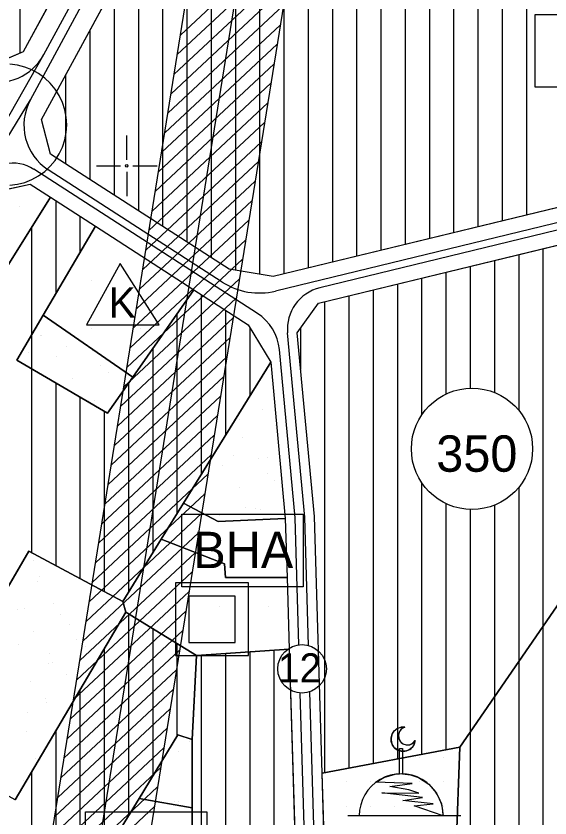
# Model space of a CAD drawing. Extents: x 419109 to 421295, y 4452223 to 4457798.
# Drawn here: x 419454.4 to 419674.5, y 4452731.2 to 4453061.8 of the extents above; entities that cross this region are included whole.
import ezdxf

# ---------------------------------------------------------------- set-up
doc = ezdxf.new("R2010")
doc.units = 0
for name, color, linetype in [('ADA', 7, 'Continuous'), ('ADAKENARI', 7, 'Continuous'), ('Default', 7, 'Continuous'), ('KALDIRIM', 7, 'Continuous'), ('KD_DAIRE', 7, 'Continuous'), ('KD_KAV_25', 7, 'Continuous'), ('KD_YGEN', 7, 'Continuous'), ('LJ_SEMBOL', 7, 'Continuous'), ('PAFTALAMA', 7, 'Continuous'), ('PL_AYA_PARK_DINLENME', 7, 'Continuous'), ('PL_K_BHA', 7, 'Continuous'), ('PL_KON_MEV_350', 7, 'Continuous'), ('PL_OZEL_DONATI', 7, 'Continuous'), ('PL_SAY_DINI_TESIS', 7, 'Continuous'), ('PL_SAY_KRES', 7, 'Continuous'), ('SM_DAIRE', 7, 'Continuous'), ('SM_TAKS', 7, 'Continuous'), ('TA_ENH_154', 7, 'Continuous'), ('TA_ENH_KORUMA', 7, 'Continuous'), ('TA_ENH_TARAMA', 7, 'Continuous'), ('TR_DINITESIS', 7, 'Continuous'), ('TR_ILKEGITIM', 7, 'Continuous'), ('TR_ORTAYOGUNKONUT', 7, 'Continuous'), ('TR_PARKALANI', 7, 'Continuous'), ('TR_SAGLIKTESIS', 7, 'Continuous'), ('TR_YONETIMMERK', 7, 'Continuous')]:
    doc.layers.add(name, color=color, linetype=linetype)

# ---------------------------------------------------------------- blocks, each defined once
blk = doc.blocks.new('POINT_DISPLAY')
at = {"layer": 'Default'}
blk.add_line((0, 0), (0, 0), dxfattribs=at)

msp = doc.modelspace()

# ---------------------------------------------------------------- linework, layer by layer
at = {"layer": 'ADA'}
for p, q in [((419468.52, 4452987.05), (419400.78, 4452878.87)), ((419465.55, 4452938.38), (419487.1, 4452975.08)), ((419527.7, 4452948.92), (419502.49, 4452912.93)), ((419454.69, 4452919.88), (419465.55, 4452938.38)), ((419465.55, 4452938.38), (419502.49, 4452912.93)), ((419492.07, 4452898.06), (419454.69, 4452919.88)), ((419559.41, 4452919.13), (419523.42, 4452860.91)), ((419502.49, 4452912.93), (419492.07, 4452898.06)), ((419523.42, 4452860.91), (419514.24, 4452846.05)), ((419537.71, 4452853.41), (419523.42, 4452860.91)), ((419565.4, 4452854.66), (419537.71, 4452853.41)), ((419514.24, 4452846.05), (419498.35, 4452820.34)), ((419514.24, 4452846.05), (419540.35, 4452835.88)), ((419459.65, 4452841.17), (419413.02, 4452761.13)), ((419498.35, 4452820.34), (419459.65, 4452841.17)), ((419540.35, 4452835.88), (419540.68, 4452830.26)), ((419540.68, 4452830.26), (419566.14, 4452830.26)), ((419498.35, 4452820.34), (419499.67, 4452816.04)), ((419454.03, 4452738.65), (419499.67, 4452816.04)), ((419499.67, 4452816.04), (419528.78, 4452798.18)), ((419528.78, 4452798.18), (419567.02, 4452800.8)), ((419521.14, 4452765.39), (419505.12, 4452739.26)), ((419526.98, 4452763.45), (419521.14, 4452765.39)), ((419526.98, 4452735.28), (419526.98, 4452763.45)), ((419580.56, 4452749.66), (419637.41, 4452760.32)), ((419637.41, 4452760.32), (419635.79, 4452719.45)), ((419505.12, 4452739.26), (419491.8, 4452717.53)), ((419505.12, 4452739.26), (419526.98, 4452735.28)), ((419526.98, 4452720.67), (419526.98, 4452735.28))]:
    msp.add_line(p, q, dxfattribs=at)
at = {"layer": 'ADAKENARI'}
for p, q in [((419521.56, 4453165.57), (419457.35, 4453047.06)), ((419464.93, 4453019.07), (419512.36, 4453106.6)), ((419457.35, 4453047.06), (419442.9, 4453040.77)), ((419468.57, 4453004.87), (419464.93, 4453019.07)), ((419799.35, 4453012.27), (419560.39, 4452954.32)), ((419542.27, 4452957.38), (419468.57, 4453004.87)), ((419579.14, 4452943.43), (419796.33, 4452996.11)), ((419446.37, 4452989.43), (419460.17, 4452992.43)), ((419460.17, 4452992.43), (419468.52, 4452987.05)), ((419468.52, 4452987.05), (419487.1, 4452975.08)), ((419487.1, 4452975.08), (419527.7, 4452948.92)), ((419560.39, 4452954.32), (419542.27, 4452957.38)), ((419527.7, 4452948.92), (419550.08, 4452934.5)), ((419570.34, 4452931.11), (419579.14, 4452943.43)), ((419550.08, 4452934.5), (419559.41, 4452919.13)), ((419577.39, 4452855.4), (419570.34, 4452931.11)), ((419559.41, 4452919.13), (419565.4, 4452854.66)), ((419580.56, 4452749.66), (419577.39, 4452855.4)), ((419565.4, 4452854.66), (419566.14, 4452830.26)), ((419566.14, 4452830.26), (419567.02, 4452800.8)), ((419567.02, 4452800.8), (419569.82, 4452707.46)), ((419581.87, 4452706.08), (419580.56, 4452749.66))]:
    msp.add_line(p, q, dxfattribs=at)
at = {"layer": 'KALDIRIM'}
for p, q in [((419465.79, 4453045.85), (419529.23, 4453162.92)), ((419460.26, 4453027.25), (419505.73, 4453111.15)), ((419446.06, 4453011.19), (419465.79, 4453045.85)), ((419439.64, 4452993.75), (419460.26, 4453027.25)), ((419553.9, 4452939.17), (419461.74, 4452998.56)), ((419539.42, 4452952.07), (419467.68, 4452998.3)), ((419680.82, 4452977.35), (419561.34, 4452948.37)), ((419682.01, 4452974.55), (419579.61, 4452949.72)), ((419573.39, 4452855.15), (419566.33, 4452931.11)), ((419569.4, 4452854.9), (419562.95, 4452924.27)), ((419574.98, 4452802.29), (419573.39, 4452855.15)), ((419570.97, 4452802.56), (419569.4, 4452854.9)), ((419573.84, 4452707), (419571.57, 4452782.68)), ((419577.86, 4452706.54), (419575.55, 4452783.19))]:
    msp.add_line(p, q, dxfattribs=at)
for centre, radius, start, end in [((419446.49, 4453056.31), 21.95, 255.5212, 331.5469), ((419479.58, 4453016.78), 21.97, 151.5469, 237.2023), ((419453.09, 4452985.13), 15.97, 57.2023, 147.3481), ((419554.69, 4452975.78), 28.2, 237.2023, 283.6329), ((419583.73, 4452932.73), 17.48, 103.6329, 185.3143), ((419543.1, 4452922.42), 19.93, 5.3143, 57.2023)]:
    msp.add_arc(centre, radius, start, end, dxfattribs=at)
at = {"layer": 'KD_DAIRE'}
msp.add_circle((419572.31, 4452792.65), 10, dxfattribs=at)
at = {"layer": 'KD_KAV_25'}
for p, q in [((419454.93, 4453041.49), (419451.82, 4453041.88)), ((419457.97, 4453040.71), (419454.93, 4453041.49)), ((419460.89, 4453039.55), (419457.97, 4453040.71)), ((419463.64, 4453038.04), (419460.89, 4453039.55)), ((419466.18, 4453036.2), (419463.64, 4453038.04)), ((419468.47, 4453034.05), (419466.18, 4453036.2)), ((419470.47, 4453031.63), (419468.47, 4453034.05)), ((419472.15, 4453028.98), (419470.47, 4453031.63)), ((419473.49, 4453026.14), (419472.15, 4453028.98)), ((419474.46, 4453023.15), (419473.49, 4453026.14)), ((419475.05, 4453020.07), (419474.46, 4453023.15)), ((419475.25, 4453016.93), (419475.05, 4453020.07)), ((419474.46, 4453010.71), (419475.05, 4453013.8)), ((419475.05, 4453013.8), (419475.25, 4453016.93)), ((419473.49, 4453007.73), (419474.46, 4453010.71)), ((419472.15, 4453004.89), (419473.49, 4453007.73)), ((419470.47, 4453002.24), (419472.15, 4453004.89)), ((419468.47, 4452999.82), (419470.47, 4453002.24)), ((419463.64, 4452995.82), (419466.18, 4452997.67)), ((419466.18, 4452997.67), (419468.47, 4452999.82)), ((419457.97, 4452993.16), (419460.89, 4452994.31)), ((419460.89, 4452994.31), (419463.64, 4452995.82)), ((419451.82, 4452991.98), (419454.93, 4452992.38)), ((419454.93, 4452992.38), (419457.97, 4452993.16))]:
    msp.add_line(p, q, dxfattribs=at)
at = {"layer": 'LJ_SEMBOL'}
for p, q in [((419668.44, 4453032.37), (419668.44, 4453032.37)), ((419497.35, 4452959.8), (419483.42, 4452934.47)), ((419513.42, 4452934.47), (419497.35, 4452959.8)), ((419483.42, 4452934.47), (419513.42, 4452934.47)), ((419550.16, 4452828.1), (419520.16, 4452828.1)), ((419520.16, 4452828.1), (419520.16, 4452798.1)), ((419522.74, 4452826.46), (419522.74, 4452826.46)), ((419550.16, 4452798.1), (419550.16, 4452828.1)), ((419544.7, 4452822.65), (419525.61, 4452822.65)), ((419525.61, 4452822.65), (419525.61, 4452803.56)), ((419544.7, 4452803.56), (419544.7, 4452822.65)), ((419525.61, 4452803.56), (419544.7, 4452803.56)), ((419520.16, 4452798.1), (419550.16, 4452798.1)), ((419637.79, 4452732.08), (419591.12, 4452732.08))]:
    msp.add_line(p, q, dxfattribs=at)
for points in [[(419668.44, 4453062.37), (419718.44, 4453062.37), (419718.44, 4453032.37), (419668.44, 4453032.37), (419668.44, 4453062.37), (419718.44, 4453062.37)], [(419522.74, 4452856.46), (419572.74, 4452856.46), (419572.74, 4452826.46), (419522.74, 4452826.46), (419522.74, 4452856.46), (419572.74, 4452856.46)], [(419483, 4452733.64), (419533, 4452733.64), (419533, 4452703.64), (419483, 4452703.64), (419483, 4452733.64), (419533, 4452733.64)]]:
    msp.add_lwpolyline(points, dxfattribs=at)
for points in [[(419520.16, 4452798.1), (419550.16, 4452798.1), (419550.16, 4452828.1), (419520.16, 4452828.1)], [(419618.96, 4452763.04), (419618.54, 4452761.54), (419617.67, 4452760.23), (419616.44, 4452759.26), (419614.97, 4452758.72), (419613.4, 4452758.66), (419611.89, 4452759.09), (419610.59, 4452759.96), (419609.63, 4452761.2), (419609.09, 4452762.67), (419609.03, 4452764.23), (419609.47, 4452765.74), (419610.34, 4452767.04), (419611.58, 4452768), (419613.05, 4452768.54), (419614.62, 4452768.59), (419613.36, 4452767.89), (419612.46, 4452766.78), (419612.05, 4452765.41), (419612.17, 4452763.98), (419612.82, 4452762.71), (419613.91, 4452761.77), (419615.26, 4452761.31), (419616.69, 4452761.38), (419617.99, 4452761.99)], [(419630.48, 4452732.1), (419618.5, 4452736.15), (419626.29, 4452737.06), (419613.85, 4452738.37), (419621.94, 4452739.63), (419605.19, 4452741.52), (419620.44, 4452741.44), (419616.27, 4452742.76), (419608.49, 4452744.19), (419617.71, 4452745.44), (419602.82, 4452745.96), (419605.99, 4452747.84), (419610.71, 4452749.23), (419612.46, 4452749.39), (419612.46, 4452759.8), (419613.71, 4452759.8), (419613.71, 4452749.39), (419616.95, 4452748.98), (419620.36, 4452747.84), (419624.51, 4452745.17), (419627.73, 4452741.45), (419629.78, 4452736.97)]]:
    msp.add_lwpolyline(points, close=True, dxfattribs=at)
for centre, radius, start, end in [((419614, 4452763.63), 5, 82.8556, 353.3219), ((419615.77, 4452765.02), 3.75, 107.9671, 328.2104), ((419613.18, 4452732.1), 17.31, 359.967, 180)]:
    msp.add_arc(centre, radius, start, end, dxfattribs=at)
at = {"layer": 'PAFTALAMA'}
for p, q in [((419500, 4453002.5), (419500, 4453012.5)), ((419487.5, 4453000), (419497.5, 4453000)), ((419500, 4452997.5), (419500, 4452987.5)), ((419502.5, 4453000), (419512.5, 4453000))]:
    msp.add_line(p, q, dxfattribs=at)
msp.add_circle((419500, 4453000), 0.5, dxfattribs=at)
at = {"layer": 'PL_AYA_PARK_DINLENME'}
for points in [[(419468.52, 4452987.05), (419400.78, 4452878.87), (419382.89, 4452878.97), (419384.68, 4452884.42), (419386.65, 4452889.8), (419388.8, 4452895.12), (419391.13, 4452900.35), (419393.63, 4452905.51), (419396.31, 4452910.58), (419399.15, 4452915.56), (419402.16, 4452920.43), (419446.37, 4452989.43), (419460.17, 4452992.43)], [(419492.07, 4452898.06), (419454.69, 4452919.88), (419465.55, 4452938.38), (419502.49, 4452912.93)], [(419559.41, 4452919.13), (419565.4, 4452854.66), (419537.71, 4452853.41), (419523.42, 4452860.91)], [(419459.65, 4452841.17), (419498.35, 4452820.34), (419499.67, 4452816.04), (419454.03, 4452738.65), (419413.02, 4452761.13)], [(419526.98, 4452735.28), (419505.12, 4452739.26), (419521.14, 4452765.39), (419526.98, 4452763.45)]]:
    msp.add_lwpolyline(points, close=True, dxfattribs=at)
at = {"layer": 'PL_K_BHA'}
for points in [[(419514.24, 4452846.05), (419523.42, 4452860.91), (419537.71, 4452853.41), (419565.4, 4452854.66), (419566.14, 4452830.26), (419540.68, 4452830.26), (419540.35, 4452835.88)], [(419523.73, 4452713.54), (419491.8, 4452717.53), (419505.12, 4452739.26), (419526.98, 4452735.28), (419526.98, 4452720.67)]]:
    msp.add_lwpolyline(points, close=True, dxfattribs=at)
at = {"layer": 'PL_KON_MEV_350'}
for points in [[(419521.56, 4453165.57), (419457.35, 4453047.06), (419442.9, 4453040.77), (419384.91, 4453055.74), (419380.18, 4453056.9), (419375.41, 4453057.95), (419370.63, 4453058.88), (419365.82, 4453059.69), (419361, 4453060.38), (419356.16, 4453060.96), (419351.3, 4453061.41), (419346.44, 4453061.75)], [(419816.16, 4453124.47), (419809.71, 4453024.61), (419799.35, 4453012.27), (419707.4, 4453034.87), (419706.89, 4453052.59), (419682.6, 4453052.08), (419684.12, 4453033.86), (419707.4, 4453034.87), (419799.35, 4453012.27), (419560.39, 4452954.32), (419542.27, 4452957.38), (419468.57, 4453004.87), (419464.93, 4453019.07), (419512.36, 4453106.6)], [(419400.78, 4452878.87), (419468.52, 4452987.05), (419487.1, 4452975.08), (419465.55, 4452938.38), (419454.69, 4452919.88), (419492.07, 4452898.06), (419502.49, 4452912.93), (419527.7, 4452948.92), (419550.08, 4452934.5), (419559.41, 4452919.13), (419523.42, 4452860.91), (419514.24, 4452846.05), (419498.35, 4452820.34), (419459.65, 4452841.17), (419413.02, 4452761.13)], [(419454.03, 4452738.65), (419499.67, 4452816.04), (419528.78, 4452798.18), (419526.98, 4452763.45), (419521.14, 4452765.39), (419505.12, 4452739.26), (419491.8, 4452717.53)], [(419526.98, 4452720.67), (419526.98, 4452763.45), (419528.78, 4452798.18), (419567.02, 4452800.8), (419569.82, 4452707.46)]]:
    msp.add_lwpolyline(points, dxfattribs=at)
msp.add_lwpolyline([(419796.33, 4452996.11), (419805.41, 4452988.48), (419786.29, 4452689.03), (419775.98, 4452676.54), (419568.88, 4452622.82), (419561.75, 4452629.97), (419581.87, 4452706.08), (419635.79, 4452719.45), (419637.41, 4452760.32), (419700.32, 4452851.73), (419754.09, 4452844.74), (419741.18, 4452876.46), (419703.54, 4452885.61), (419700.32, 4452851.73), (419637.41, 4452760.32), (419580.56, 4452749.66), (419577.39, 4452855.4), (419570.34, 4452931.11), (419579.14, 4452943.43)], close=True, dxfattribs=at)
at = {"layer": 'PL_OZEL_DONATI'}
msp.add_lwpolyline([(419567.02, 4452800.8), (419528.78, 4452798.18), (419499.67, 4452816.04), (419498.35, 4452820.34), (419514.24, 4452846.05), (419540.35, 4452835.88), (419540.68, 4452830.26), (419566.14, 4452830.26)], close=True, dxfattribs=at)
at = {"layer": 'PL_SAY_DINI_TESIS'}
msp.add_lwpolyline([(419580.56, 4452749.66), (419637.41, 4452760.32), (419635.79, 4452719.45), (419581.87, 4452706.08)], close=True, dxfattribs=at)
at = {"layer": 'PL_SAY_KRES'}
msp.add_lwpolyline([(419487.1, 4452975.08), (419527.7, 4452948.92), (419502.49, 4452912.93), (419465.55, 4452938.38)], close=True, dxfattribs=at)
at = {"layer": 'SM_DAIRE'}
msp.add_circle((419642.37, 4452883.33), 25, dxfattribs=at)
at = {"layer": 'TA_ENH_154'}
msp.add_lwpolyline([(421244.23, 4452871.73), (420603.45, 4452866.93), (420104.11, 4452747.15), (419709.07, 4452649.72), (419353.3, 4452559.56), (419284.53, 4452601.29), (419287.68, 4452599.87), (419484.08, 4452691.72), (419833.95, 4454863.94), (419862.83, 4455014.24)], dxfattribs=at)
at = {"layer": 'TA_ENH_KORUMA'}
msp.add_line((419466.02, 4452705.35), (419814.25, 4454867.42), dxfattribs=at)
msp.add_lwpolyline([(419883.15, 4455014.02), (419853.65, 4454860.46), (419502.14, 4452678.09), (419329.55, 4452597.37), (419356.51, 4452581.01), (419704.22, 4452669.12), (420099.38, 4452766.58), (420601.01, 4452886.92), (421244.44, 4452891.74)], dxfattribs=at)
at = {"layer": 'TA_ENH_TARAMA'}
for p, q in [((419522.15, 4453053.89), (419569.85, 4453098.47)), ((419520.85, 4453045.83), (419568.55, 4453090.41)), ((419519.55, 4453037.77), (419567.25, 4453082.35)), ((419518.26, 4453029.72), (419565.96, 4453074.3)), ((419516.96, 4453021.66), (419564.66, 4453066.24)), ((419515.66, 4453013.6), (419563.36, 4453058.18)), ((419514.36, 4453005.55), (419562.06, 4453050.12)), ((419513.07, 4452997.49), (419560.77, 4453042.07)), ((419511.77, 4452989.43), (419559.47, 4453034.01)), ((419510.47, 4452981.37), (419558.17, 4453025.95)), ((419509.17, 4452973.32), (419556.87, 4453017.9)), ((419507.88, 4452965.26), (419555.57, 4453009.84)), ((419506.58, 4452957.2), (419554.28, 4453001.78)), ((419505.28, 4452949.15), (419552.98, 4452993.72)), ((419503.98, 4452941.09), (419551.68, 4452985.67)), ((419502.68, 4452933.03), (419550.38, 4452977.61)), ((419501.39, 4452924.97), (419549.09, 4452969.55)), ((419500.09, 4452916.92), (419547.79, 4452961.5)), ((419498.79, 4452908.86), (419546.49, 4452953.44)), ((419497.49, 4452900.8), (419545.19, 4452945.38)), ((419496.2, 4452892.75), (419543.9, 4452937.32)), ((419494.9, 4452884.69), (419542.6, 4452929.27)), ((419493.6, 4452876.63), (419541.3, 4452921.21)), ((419492.3, 4452868.57), (419540, 4452913.15)), ((419491.01, 4452860.52), (419538.7, 4452905.1)), ((419489.71, 4452852.46), (419537.41, 4452897.04)), ((419488.41, 4452844.4), (419536.11, 4452888.98)), ((419487.11, 4452836.35), (419534.81, 4452880.92)), ((419485.81, 4452828.29), (419533.51, 4452872.87)), ((419484.52, 4452820.23), (419532.22, 4452864.81)), ((419483.22, 4452812.17), (419530.92, 4452856.75)), ((419481.92, 4452804.12), (419529.62, 4452848.7)), ((419480.62, 4452796.06), (419528.32, 4452840.64)), ((419479.33, 4452788), (419527.03, 4452832.58)), ((419478.03, 4452779.95), (419525.73, 4452824.52)), ((419476.73, 4452771.89), (419524.43, 4452816.47)), ((419475.43, 4452763.83), (419523.13, 4452808.41)), ((419474.14, 4452755.77), (419521.83, 4452800.35)), ((419472.84, 4452747.72), (419520.54, 4452792.3)), ((419471.54, 4452739.66), (419519.24, 4452784.24)), ((419470.24, 4452731.6), (419517.94, 4452776.18)), ((419468.94, 4452723.55), (419516.64, 4452768.12)), ((419467.65, 4452715.49), (419515.35, 4452760.07)), ((419466.35, 4452707.43), (419514.05, 4452752.01)), ((419382.31, 4452622.04), (419512.75, 4452743.95)), ((419396.97, 4452628.9), (419511.45, 4452735.9))]:
    msp.add_line(p, q, dxfattribs=at)
at = {"layer": 'TR_ORTAYOGUNKONUT'}
for p, q in [((419644.93, 4452974.82), (419644.93, 4453230.01)), ((419654.93, 4452977.25), (419654.93, 4453227.48)), ((419664.93, 4452979.67), (419664.93, 4453224.95)), ((419584.93, 4452960.27), (419584.93, 4453191.7)), ((419456.12, 4453046.52), (419456.12, 4453185.83)), ((419574.93, 4452957.84), (419574.93, 4453179.97)), ((419564.93, 4452955.42), (419564.93, 4453168.25)), ((419554.93, 4452955.24), (419554.93, 4453156.52)), ((419544.93, 4452956.93), (419544.93, 4453144.79)), ((419534.93, 4452962.1), (419534.93, 4453133.07)), ((419524.93, 4452968.55), (419524.93, 4453121.34)), ((419514.93, 4452974.99), (419514.93, 4453109.61)), ((419504.93, 4452981.44), (419504.93, 4453092.89)), ((419494.93, 4452987.88), (419494.93, 4453074.44)), ((419594.93, 4452962.69), (419594.93, 4453075.84)), ((419634.93, 4452972.39), (419634.93, 4453076.56)), ((419604.93, 4452965.12), (419604.93, 4453068.16)), ((419624.93, 4452969.97), (419624.93, 4453068.4)), ((419614.93, 4452967.54), (419614.93, 4453066.19)), ((419484.93, 4452994.32), (419484.93, 4453055.98)), ((419474.93, 4453000.77), (419474.93, 4453037.53)), ((419470.85, 4452947.41), (419470.85, 4452985.55)), ((419480.85, 4452964.44), (419480.85, 4452979.1)), ((419460.85, 4452930.38), (419460.85, 4452974.81)), ((419460.85, 4452840.53), (419460.85, 4452974.81)), ((419671.75, 4452649.5), (419671.75, 4452965.89)), ((419651.75, 4452906.51), (419651.75, 4452961.04)), ((419661.75, 4452899.12), (419661.75, 4452963.47)), ((419641.75, 4452908.32), (419641.75, 4452958.61)), ((419631.75, 4452905.96), (419631.75, 4452956.19)), ((419611.75, 4452755.51), (419611.75, 4452951.34)), ((419621.75, 4452897.47), (419621.75, 4452953.76)), ((419601.75, 4452753.63), (419601.75, 4452948.91)), ((419530.85, 4452872.93), (419530.85, 4452946.88)), ((419591.75, 4452751.76), (419591.75, 4452946.49)), ((419581.75, 4452749.88), (419581.75, 4452944.06)), ((419520.85, 4452856.75), (419520.85, 4452939.14)), ((419540.85, 4452889.11), (419540.85, 4452940.44)), ((419550.85, 4452905.29), (419550.85, 4452933.22)), ((419571.75, 4452915.98), (419571.75, 4452933.09)), ((419510.85, 4452840.57), (419510.85, 4452924.87)), ((419470.85, 4452835.14), (419470.85, 4452910.45)), ((419500.85, 4452824.39), (419500.85, 4452910.6)), ((419480.85, 4452829.76), (419480.85, 4452904.6)), ((419490.85, 4452824.37), (419490.85, 4452898.76)), ((419621.75, 4452757.38), (419621.75, 4452869.2)), ((419661.75, 4452646.91), (419661.75, 4452867.54)), ((419631.75, 4452759.26), (419631.75, 4452860.7)), ((419651.75, 4452644.31), (419651.75, 4452860.16)), ((419641.75, 4452641.72), (419641.75, 4452858.34)), ((419500.85, 4452732.3), (419500.85, 4452815.31)), ((419510.85, 4452748.61), (419510.85, 4452809.17)), ((419520.85, 4452764.92), (419520.85, 4452803.04)), ((419490.85, 4452715.99), (419490.85, 4452801.08)), ((419540.85, 4452618.98), (419540.85, 4452799.01)), ((419550.85, 4452635.7), (419550.85, 4452799.69)), ((419560.85, 4452673.53), (419560.85, 4452800.38)), ((419530.85, 4452612.95), (419530.85, 4452798.32)), ((419480.85, 4452699.69), (419480.85, 4452784.13)), ((419470.85, 4452683.38), (419470.85, 4452767.17)), ((419460.85, 4452607.72), (419460.85, 4452750.21))]:
    msp.add_line(p, q, dxfattribs=at)

# ---------------------------------------------------------------- block references
at = {"layer": 'TR_DINITESIS', "xscale": 0.1, "yscale": 0.10000000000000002}
for p in [(419620.56, 4452756.08), (419630.56, 4452756.08), (419590.56, 4452746.08), (419600.56, 4452746.08), (419610.56, 4452746.08), (419620.56, 4452746.08), (419630.56, 4452746.08), (419590.56, 4452736.08), (419600.56, 4452736.08), (419610.56, 4452736.08), (419620.56, 4452736.08), (419630.56, 4452736.08)]:
    msp.add_blockref('POINT_DISPLAY', p, dxfattribs=at)
at = {"layer": 'TR_ILKEGITIM', "xscale": 0.1, "yscale": 0.10000000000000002}
for p in [(419485.55, 4452952.93), (419505.55, 4452952.93), (419485.55, 4452932.93), (419505.55, 4452932.93)]:
    msp.add_blockref('POINT_DISPLAY', p, dxfattribs=at)
at = {"layer": 'TR_PARKALANI', "xscale": 0.1, "yscale": 0.10000000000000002}
for p in [(419455.9, 4452983.14), (419464.26, 4452930.21), (419464.89, 4452929.93), (419475.33, 4452925.38), (419459.69, 4452923.06), (419485.69, 4452923.83), (419470.92, 4452921.23), (419489.24, 4452917.85), (419492.35, 4452914.85), (419477.58, 4452912.25), (419484.24, 4452903.27), (419486.63, 4452903.08), (419555.87, 4452899.75), (419546.67, 4452895.5), (419561.44, 4452892.89), (419547.76, 4452888.16), (419544.07, 4452880.73), (419554.42, 4452879.18), (419557.97, 4452879.6), (419539.65, 4452876.58), (419557.97, 4452873.2), (419561.08, 4452870.2), (419546.31, 4452867.6), (419531.54, 4452864.99), (419549.08, 4452859.09), (419552.97, 4452858.62), (419555.36, 4452858.43), (419538.2, 4452856.01), (419539.72, 4452856.11), (419461.46, 4452837.22), (419463.14, 4452828.72), (419463.99, 4452830.84), (419477.91, 4452831.32), (419484.58, 4452822.34), (419488.34, 4452825.16), (419469.8, 4452819.74), (419455.03, 4452817.13), (419457.98, 4452817.52), (419488.4, 4452817.24), (419472.76, 4452814.92), (419491.24, 4452813.36), (419476.46, 4452810.76), (419461.69, 4452808.15), (419455.38, 4452802.75), (419479.44, 4452804.64), (419468.35, 4452799.17), (419483.12, 4452801.78), (419467.95, 4452795), (419469.28, 4452795.22), (419484.06, 4452792.62), (419475.01, 4452790.19), (419460.24, 4452787.59), (419466.68, 4452780.45), (419466.9, 4452778.61), (419459.06, 4452774.48), (419458.79, 4452767.02), (419525.76, 4452762.6), (419465.45, 4452758.04), (419521.34, 4452758.45), (419462.34, 4452755.83), (419457.34, 4452746.46), (419513.23, 4452746.87), (419506.64, 4452740.59), (419519.89, 4452737.89), (419521.42, 4452737.98)]:
    msp.add_blockref('POINT_DISPLAY', p, dxfattribs=at)
at = {"layer": 'TR_SAGLIKTESIS', "xscale": 0.1, "yscale": 0.10000000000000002}
for p in [(419518.35, 4452838.18), (419518.35, 4452818.18), (419538.35, 4452818.18), (419558.35, 4452818.18)]:
    msp.add_blockref('POINT_DISPLAY', p, dxfattribs=at)
at = {"layer": 'TR_YONETIMMERK', "xscale": 0.1, "yscale": 0.10000000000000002}
msp.add_blockref('POINT_DISPLAY', (419564.24, 4452830.26), dxfattribs=at)

# ---------------------------------------------------------------- texts
at = {"layer": 'KD_YGEN'}
msp.add_text('12', height=12, dxfattribs=at).set_placement((419562.34, 4452787.04))
at = {"layer": 'LJ_SEMBOL'}
for s, height, p in [('K', 12.5, (419492.56, 4452937.38)), ('BHA', 15, (419527.44, 4452834.15))]:
    msp.add_text(s, height=height, dxfattribs=at).set_placement(p)
at = {"layer": 'SM_TAKS'}
msp.add_text('350', height=15, dxfattribs=at).set_placement((419627.63, 4452873.89))

doc.saveas('drawing.dxf')
